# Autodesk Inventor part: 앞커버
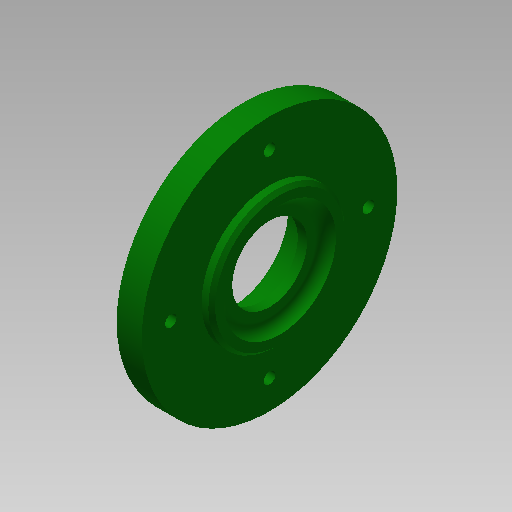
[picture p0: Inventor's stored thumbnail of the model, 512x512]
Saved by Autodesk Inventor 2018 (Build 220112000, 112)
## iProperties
Created: 2015-09
Part Number: 앞커버
Material: 알루미늄 6061
Document SubType Name: Modeling
Designer: mduedu
Density: 2.71 g/cm^3
Mass: 58.9874 g
Surface Area: 98.7754 cm^2
Volume: 21.7666 cm^3
Appearance: 진녹색
Author: mduedu
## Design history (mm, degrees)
sketch "스케치1"
  geometry: L1 (-8.5, 67)-(-11.5, 67); L2 (-11.5, 67)-(-11.5, 84.5); L3 (-11.5, 84.5)-(-19.5, 84.5); L4 (-19.5, 84.5)-(-19.5, 70.5); L5 (-22.5, 70.5)-(-22.5, 58); L6 (-22.5, 58)-(-8.5, 58); L7 (-8.5, 58)-(-8.5, 67); L8 (-79.5, 39.5)-(-79.5, 54.5) reference; L9 (48.5, 54.5)-(48.5, 39.5) reference; L10 (-79.5, 47)-(48.5, 47); L11 (-19.5, 70.5)-(-22.5, 70.5); 3 further points
  constraints: 18 end point, 6 parallel, 4 midpoint, 1 horizontal, 1 perpendicular, 1 vertical alignment
  dimensions: "d0" = 14 distance between parallel lines of L7 L5; "d2" = 22 diameter of L6 L10; "d3" = 40 diameter of L1 L10; "d5" = 3 distance of L1.start L1.end; "d6" = 75 diameter of L3 L10; "d7" = 8 distance of L2.end L3.end; "d8" = 47 diameter of L4.end L10
revolve "회전1" sketch "스케치1" stored, may be unused: angle "d4" = 90 deg
sketch "스케치2"
  geometry: C1 r 37.5 at (0, 0) reference; 2 further points
  constraints: 1 coincident
hole "구멍1" sketch "스케치2" at (0, 0) diameter "d11" = 33; stored, may be unused: countersink angle "d15" = 90 deg, drill point angle "d17" = 0 deg; dims "d12" = 6, "d13" = 4, "d14" = 2, "d16" = 3
fillet "모깎기1" dims "d18" = 3
fillet "모깎기2" dims "d19" = 1
sketch "스케치3"
  geometry: C1 r 37.5 at (0, 0) reference; 2 further points
  constraints: 1 coincident
hole "구멍2" sketch "스케치3" at (0, 0) diameter "d20" = 32; stored, may be unused: countersink angle "d24" = 90 deg, drill point angle "d26" = 0 deg; dims "d21" = 6, "d22" = 4, "d23" = 2, "d25" = 8.3
fillet "모깎기3" dims "d27" = 0.4
chamfer "모따기1" distance "d28" = 0.8; stored, may be unused: second distance "d29" = 2, angle "d30" = 30 deg
sketch "스케치7" dims "d56" = 58
  geometry: C1 r 37.5 at (0, 0) reference; 5 further points
  constraints: 2 vertical alignment, 1 coincident, 7 other
  dimensions: "d59" = 360 deg dimension on C1.centre point (0, 29) (derived)
hole "구멍4" sketch "스케치7" at (0, 29), (-29, 0), (0, -29), (29, 0) diameter "d48" = 3.4; stored, may be unused: countersink angle "d52" = 90 deg, drill point angle "d54" = 0 deg; dims "d49" = 6, "d50" = 6.5, "d51" = 3.4, "d53" = 8
chamfer "모따기2" distance "d61" = 1; stored, may be unused: second distance "d62" = 2, angle "d63" = 45 deg
node "솔리드1"
node "참조1"
node "참조2"
